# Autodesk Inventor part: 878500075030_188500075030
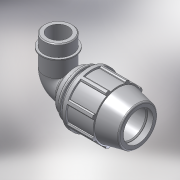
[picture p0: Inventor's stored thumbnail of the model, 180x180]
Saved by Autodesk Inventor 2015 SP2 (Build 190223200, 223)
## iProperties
Created: 2017-02
Part Number: 878500075030_188500075030
Material: PVC-Piping
Description: PLASSON 90° ELBOW MALE ADAPTOR 75-3"
Document SubType Name: Modeling
Designer: KIM
Mass: 92.6774 g
Surface Area: 199.44 cm^2
Volume: 66.1981 cm^3
Density: 1.4 g/cm^3
Appearance: Smooth - White
Author: KIM
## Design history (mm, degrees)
derived "87850.ipt"
feature "Solid1::87850.ipt"
tag "TaggingFeature1"
body "Solid1"
other parameters: "d2" = 75, "d4" = 17.25, "d5" = 51.75, "d7" = 132, "d9" = 29.57143, "d11" = 6.9, "d13" = 120 deg, "d14" = 97.5, "d15" = 12 deg, "d16" = 114.84, "d18" = 3.75, "d19" = 35 deg, "d20" = 17.5 deg, "d21" = 122.76, "d23" = 0, "d25" = 360 deg, "d27" = 2.64, "d33" = 1.5, "d42" = 76.59, "d43" = 3.96, "d46" = 2.25, "d51" = 207, "d68" = 13.8, "d73" = 87.884, "d74" = 33, "d75" = 101.0666, "d76" = 61.5188, "d77" = 36.3, "d79" = 35.1536, "d80" = 2.63652, "d83" = 0, "d84" = 0, "d91" = 99, "d93" = 137, "d94" = 87.884, "d95" = 61.5188, "d96" = 13.8, "d97" = 50 deg, "d98" = 3.45, "d99" = 111.3948, "d100" = 3.45, "d101" = 3.45, "d102" = 8.8, "d103" = 0, "d_" = 75, "E_" = 132, "A_" = 207, "l_" = 137, "l_2" = 33, "G_" = 87.884
